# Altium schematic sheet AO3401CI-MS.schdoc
size 127 x 101 mm
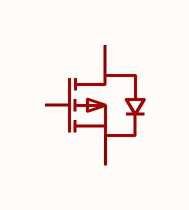
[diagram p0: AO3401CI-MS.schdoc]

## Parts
Q?  ao3401ci-ms  [SOT-23-3_L2.9-W1.3-P1.90-LS2.4-BR]  (value not drawn)

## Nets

Not connected (* = marked no-connect by the designer): Q? 1(G) 2(S) 3(D)

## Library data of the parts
Q? = ao3401ci-ms: 数量:1个P沟道;漏源电压(Vdss):20V;连续漏极电流(Id):3A;导通电阻(RDS(on)):58mΩ@4.5V;耗散功率(Pd):1W;阈值电压(Vgs(th)):700mV;; Manufacturer: MSKSEMI(美森科); AddInBom: yes; ModelId: c62791f0466c4ae2a892c056b845b0ca; ModelName: SOT-23-3P_L2.9-W1.3-H1.0-LS2.4-P0.95; ModelTransform: 98.425,114.173,0,180,0,0,0.0005,-0.0005,0; Number: 1个P沟道; Drain to Source Voltage: 20V; Current - Continuous Drain(Id): 3A; Pd - Power Dissipation: 1W; Gate Threshold Voltage (Vgs(th)): 700mV; Gate Charge(Qg): 4.1nC@4.5V; Input Capacitance(Ciss): 503pF; Reverse Transfer Capacitance (Crss@Vds): 58pF; Type: P沟道; Output Capacitance(Coss): 67pF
